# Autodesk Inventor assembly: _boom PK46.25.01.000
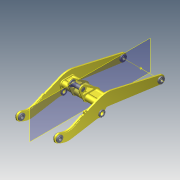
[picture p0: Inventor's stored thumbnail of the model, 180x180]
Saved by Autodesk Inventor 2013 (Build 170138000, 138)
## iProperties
Created: 2005-04
Part Number: _boom PK46.25.01.000
Document SubType Name: Assembly
Designer: salex
Manufacturer: Standard
Standards Organization: Custom
Author: salex
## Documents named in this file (13)
- C:\Product Design Suite 2013 Test Drive\Inventor to Showcase\Workspace\Assy, Chassis, Front\_boom PK46.25.01.000.iam
- C:\Product Design Suite 2013 Test Drive\Inventor to Showcase\Workspace\Assy, Chassis, Front\PK46.25.01.011.ipt
- C:\Product Design Suite 2013 Test Drive\Inventor to Showcase\Workspace\Assy, Chassis, Front\PK46.25.01.013.ipt
- C:\Product Design Suite 2013 Test Drive\Inventor to Showcase\Workspace\Assy, Chassis, Front\PK46.25.01.014.ipt
- C:\Product Design Suite 2013 Test Drive\Inventor to Showcase\Workspace\Assy, Chassis, Front\PK46.25.01.015.ipt
- C:\Product Design Suite 2013 Test Drive\Inventor to Showcase\Workspace\Assy, Chassis, Front\M10-6H.5.019(S16).ipt
- C:\Product Design Suite 2013 Test Drive\Inventor to Showcase\Workspace\Assy, Chassis, Front\10.65G.019.ipt
- C:\Product Design Suite 2013 Test Drive\Inventor to Showcase\Workspace\Assy, Chassis, Front\PK46.25.01.010.iam
- C:\Product Design Suite 2013 Test Drive\Inventor to Showcase\Workspace\Assy, Chassis, Front\PK46.25.00.030.iam
- C:\Product Design Suite 2013 Test Drive\Inventor to Showcase\Workspace\Assy, Chassis, Front\PK46.25.00.008.ipt
- C:\Product Design Suite 2013 Test Drive\Inventor to Showcase\Workspace\Assy, Chassis, Front\PK46.25.00.007.ipt
- M10-6H.5.019(S16).ipt
- 10.65G.019.ipt
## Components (38 placed, 10 different names)
1. _PK46.25.01.010:1 [sub-assembly] — Insert:1, Insert:2, Insert:3, Insert:4, Insert:5, Insert:6, Insert:7, Insert:8, Insert:13, Insert:14, Insert:15, Insert:16, Mate:1, Mate:2, Mate:3, Mate:4, Mate:7, Flush:4, Flush:5, Mate:14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
2. PK46.25.00.030:1 [sub-assembly]
3. PK46.25.00.008:1
4. PK46.25.00.007:1
5. PK46.25.01.011:1 — Insert:2
6. PK46.25.01.011:2 — Insert:1
7. PK46.25.01.011:3 — Insert:7
8. PK46.25.01.011:4 — Insert:8, Flush:8
9. PK46.25.01.011:5 — Insert:6, Flush:2
10. PK46.25.01.011:6 — Insert:5
11. PK46.25.01.011:7 — Insert:4, Flush:3
12. PK46.25.01.011:8 — Insert:3
13. PK46.25.01.013:1 — Insert:9
14. PK46.25.01.013:2 — Insert:10
15. PK46.25.01.013:3 — Insert:11
16. PK46.25.01.013:4 — Insert:12
17. PK46.25.01.014:1 — Insert:9, Insert:13, Mate:3
18. PK46.25.01.014:2 — Insert:10, Insert:15, Mate:4, Insert:34, Insert:33, Insert:32, Insert:31, Insert:30, Insert:29
19. PK46.25.01.014:3 — Insert:11, Insert:14, Mate:2, Flush:6
20. PK46.25.01.014:4 — Insert:12, Insert:16, Mate:1, Insert:23, Insert:24, Insert:25, Insert:26, Insert:27, Insert:28
21. PK46.25.01.015:1 — Insert:23
22. PK46.25.01.015:2 — Insert:24
23. PK46.25.01.015:3 — Insert:25
24. PK46.25.01.015:4 — Insert:26
25. PK46.25.01.015:5 — Insert:27
26. PK46.25.01.015:6 — Insert:28
27. M10-6H.5.019(S16):1 — Insert:22
28. M10-6H.5.019(S16):2 — Insert:21
29. M10-6H.5.019(S16):3 — Insert:20
30. M10-6H.5.019(S16):4 — Insert:19
31. M10-6H.5.019(S16):5 — Insert:18
32. M10-6H.5.019(S16):6 — Insert:17
33. 10.65G.019:1 — Insert:22, Insert:34
34. 10.65G.019:2 — Insert:21, Insert:33
35. 10.65G.019:3 — Insert:20, Insert:32
36. 10.65G.019:4 — Insert:19, Insert:31
37. 10.65G.019:5 — Insert:18, Insert:30
38. 10.65G.019:6 — Insert:17, Insert:29
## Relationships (49: Insert 34, Mate 8, Flush 7)
- Insert:1: _PK46.25.01.010:1 ↔ PK46.25.01.011:2
- Insert:2: _PK46.25.01.010:1 ↔ PK46.25.01.011:1
- Insert:3: _PK46.25.01.010:1 ↔ PK46.25.01.011:8
- Insert:4: _PK46.25.01.010:1 ↔ PK46.25.01.011:7
- Insert:5: _PK46.25.01.010:1 ↔ PK46.25.01.011:6
- Insert:6: _PK46.25.01.010:1 ↔ PK46.25.01.011:5
- Insert:7: _PK46.25.01.010:1 ↔ PK46.25.01.011:3
- Insert:8: _PK46.25.01.010:1 ↔ PK46.25.01.011:4
- Insert:9: PK46.25.01.013:1 ↔ PK46.25.01.014:1
- Insert:10: PK46.25.01.013:2 ↔ PK46.25.01.014:2
- Insert:11: PK46.25.01.013:3 ↔ PK46.25.01.014:3
- Insert:12: PK46.25.01.013:4 ↔ PK46.25.01.014:4
- Insert:13: _PK46.25.01.010:1 ↔ PK46.25.01.014:1
- Insert:14: _PK46.25.01.010:1 ↔ PK46.25.01.014:3
- Insert:15: _PK46.25.01.010:1 ↔ PK46.25.01.014:2
- Insert:16: _PK46.25.01.010:1 ↔ PK46.25.01.014:4
- Mate:1: _PK46.25.01.010:1 ↔ PK46.25.01.014:4
- Mate:2: _PK46.25.01.010:1 ↔ PK46.25.01.014:3
- Mate:3: _PK46.25.01.010:1 ↔ PK46.25.01.014:1
- Mate:4: _PK46.25.01.010:1 ↔ PK46.25.01.014:2
- Insert:17: M10-6H.5.019(S16):6 ↔ 10.65G.019:6
- Insert:18: M10-6H.5.019(S16):5 ↔ 10.65G.019:5
- Insert:19: M10-6H.5.019(S16):4 ↔ 10.65G.019:4
- Insert:20: M10-6H.5.019(S16):3 ↔ 10.65G.019:3
- Insert:21: M10-6H.5.019(S16):2 ↔ 10.65G.019:2
- Insert:22: M10-6H.5.019(S16):1 ↔ 10.65G.019:1
- Insert:23: PK46.25.01.014:4 ↔ PK46.25.01.015:1
- Insert:24: PK46.25.01.014:4 ↔ PK46.25.01.015:2
- Insert:25: PK46.25.01.014:4 ↔ PK46.25.01.015:3
- Insert:26: PK46.25.01.014:4 ↔ PK46.25.01.015:4
- Insert:27: PK46.25.01.014:4 ↔ PK46.25.01.015:5
- Insert:28: PK46.25.01.014:4 ↔ PK46.25.01.015:6
- Insert:34: PK46.25.01.014:2 ↔ 10.65G.019:1
- Insert:33: PK46.25.01.014:2 ↔ 10.65G.019:2
- Insert:32: PK46.25.01.014:2 ↔ 10.65G.019:3
- Insert:31: PK46.25.01.014:2 ↔ 10.65G.019:4
- Insert:30: PK46.25.01.014:2 ↔ 10.65G.019:5
- Insert:29: PK46.25.01.014:2 ↔ 10.65G.019:6
- Flush:2: PK46.25.01.011:5
- Mate:7: _PK46.25.01.010:1
- Flush:3: PK46.25.01.011:7
- Flush:4: _PK46.25.01.010:1
- Flush:5: _PK46.25.01.010:1
- Mate:14: _PK46.25.01.010:1
- Flush:6: PK46.25.01.014:3
- Mate:17: _PK46.25.01.010:1
- Flush:7: _PK46.25.01.010:1
- Flush:8: PK46.25.01.011:4
- Mate:20: _PK46.25.01.010:1
